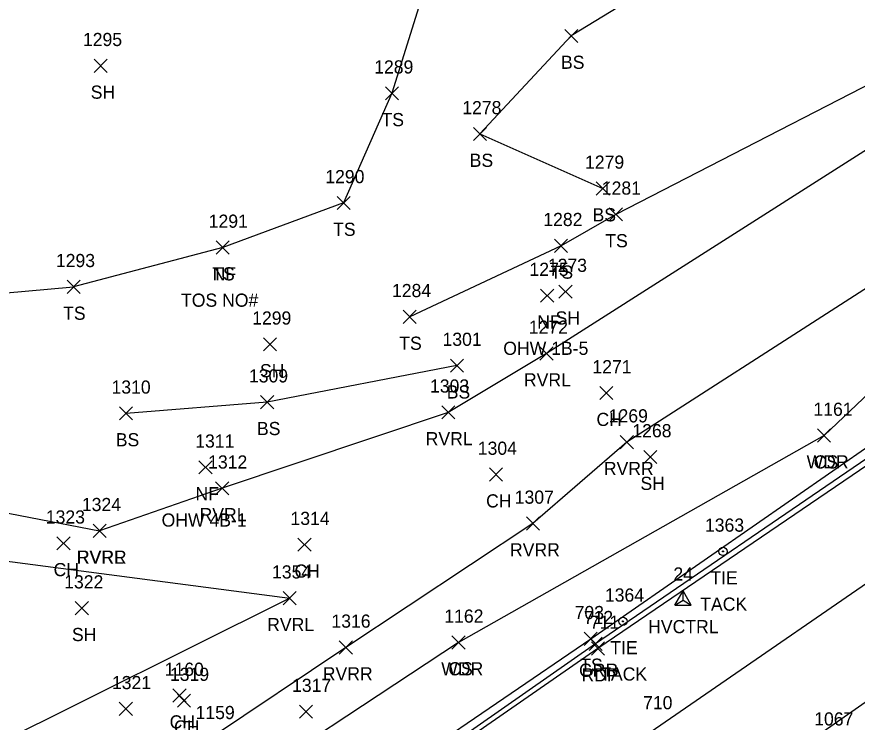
# Model space of a CAD drawing. Extents: x 1528286 to 1556263, y 492387 to 508952.
# Drawn here: x 1528810.2 to 1528937.9, y 492961.3 to 493068.5 of the extents above; entities that cross this region are included whole.
import ezdxf

# ---------------------------------------------------------------- set-up
doc = ezdxf.new("R2010")
doc.units = 0
for name, color, linetype in [('C_A', 7, 'Continuous'), ('C_C', 7, 'Continuous'), ('C_I', 7, 'Continuous'), ('CBP', 7, 'Continuous'), ('CPSM', 7, 'Continuous'), ('L_A', 7, 'Continuous'), ('L_C', 7, 'Continuous'), ('L_I', 7, 'Continuous'), ('L_TIC', 7, 'Continuous'), ('LAWA', 7, 'Continuous'), ('LAWE', 7, 'Continuous'), ('LELB', 7, 'Continuous'), ('P_A', 7, 'Continuous'), ('P_I', 7, 'Continuous'), ('P_TIC', 7, 'Continuous'), ('PET', 7, 'Continuous'), ('PRC', 7, 'Continuous'), ('R_A', 7, 'Continuous'), ('R_I', 7, 'Continuous'), ('R_TIC', 7, 'Continuous'), ('RGR', 7, 'Continuous')]:
    doc.layers.add(name, color=color, linetype=linetype)

msp = doc.modelspace()

# ---------------------------------------------------------------- linework, layer by layer
at = {"layer": 'CBP'}
for centre, radius in [((1528917.47, 492987.26), 0.625), ((1528917.47, 492987.26), 0.625), ((1528917.47, 492987.26), 0.0833), ((1528917.47, 492987.26), 0.0833), ((1528902.27, 492976.64), 0.625), ((1528902.27, 492976.64), 0.625), ((1528902.27, 492976.64), 0.0833), ((1528902.27, 492976.64), 0.0833)]:
    msp.add_circle(centre, radius, dxfattribs=at)
at = {"layer": 'CPSM'}
for p, q in [((1528910.16, 492979.12), (1528911.41, 492981.29)), ((1528910.16, 492979.12), (1528911.41, 492981.29)), ((1528912.66, 492979.12), (1528911.41, 492981.29)), ((1528911.41, 492979.84), (1528911.41, 492981.29)), ((1528912.66, 492979.12), (1528911.41, 492981.29)), ((1528911.41, 492979.84), (1528911.41, 492981.29)), ((1528910.16, 492979.12), (1528911.41, 492979.84)), ((1528910.16, 492979.12), (1528911.41, 492979.84)), ((1528910.16, 492979.12), (1528912.66, 492979.12)), ((1528910.16, 492979.12), (1528912.66, 492979.12)), ((1528911.41, 492979.84), (1528911.41, 492979.84)), ((1528911.41, 492979.84), (1528912.66, 492979.12)), ((1528911.41, 492979.84), (1528911.41, 492979.84)), ((1528911.41, 492979.84), (1528912.66, 492979.12))]:
    msp.add_line(p, q, dxfattribs=at)
at = {"layer": 'L_TIC'}
for points in [[(1528893.42, 493064.57), (1528895.42, 493066.57)], [(1528895.42, 493064.57), (1528893.42, 493066.57)], [(1528893.42, 493064.57), (1528895.42, 493066.57)], [(1528895.42, 493064.57), (1528893.42, 493066.57)], [(1528821.92, 493060.03), (1528823.92, 493062.03)], [(1528823.92, 493060.03), (1528821.92, 493062.03)], [(1528821.92, 493060.03), (1528823.92, 493062.03)], [(1528823.92, 493060.03), (1528821.92, 493062.03)], [(1528866.18, 493055.86), (1528868.18, 493057.86)], [(1528868.18, 493055.86), (1528866.18, 493057.86)], [(1528866.18, 493055.86), (1528868.18, 493057.86)], [(1528868.18, 493055.86), (1528866.18, 493057.86)], [(1528879.55, 493049.68), (1528881.55, 493051.68)], [(1528881.55, 493049.68), (1528879.55, 493051.68)], [(1528879.55, 493049.68), (1528881.55, 493051.68)], [(1528881.55, 493049.68), (1528879.55, 493051.68)], [(1528898.21, 493041.4), (1528900.21, 493043.4)], [(1528900.21, 493041.4), (1528898.21, 493043.4)], [(1528898.21, 493041.4), (1528900.21, 493043.4)], [(1528900.21, 493041.4), (1528898.21, 493043.4)], [(1528858.83, 493039.2), (1528860.83, 493041.2)], [(1528860.83, 493039.2), (1528858.83, 493041.2)], [(1528858.83, 493039.2), (1528860.83, 493041.2)], [(1528860.83, 493039.2), (1528858.83, 493041.2)], [(1528900.19, 493037.46), (1528902.19, 493039.46)], [(1528902.19, 493037.46), (1528900.19, 493039.46)], [(1528900.19, 493037.46), (1528902.19, 493039.46)], [(1528902.19, 493037.46), (1528900.19, 493039.46)], [(1528840.46, 493032.43), (1528842.46, 493034.43)], [(1528842.46, 493032.43), (1528840.46, 493034.43)], [(1528840.46, 493032.43), (1528842.46, 493034.43)], [(1528842.46, 493032.43), (1528840.46, 493034.43)], [(1528840.46, 493032.43), (1528842.46, 493034.43)], [(1528842.46, 493032.43), (1528840.46, 493034.43)], [(1528840.46, 493032.43), (1528842.46, 493034.43)], [(1528842.46, 493032.43), (1528840.46, 493034.43)], [(1528891.87, 493032.69), (1528893.87, 493034.69)], [(1528893.87, 493032.69), (1528891.87, 493034.69)], [(1528891.87, 493032.69), (1528893.87, 493034.69)], [(1528893.87, 493032.69), (1528891.87, 493034.69)], [(1528817.81, 493026.45), (1528819.81, 493028.45)], [(1528819.81, 493026.45), (1528817.81, 493028.45)], [(1528817.81, 493026.45), (1528819.81, 493028.45)], [(1528819.81, 493026.45), (1528817.81, 493028.45)], [(1528892.55, 493025.73), (1528894.55, 493027.73)], [(1528894.55, 493025.73), (1528892.55, 493027.73)], [(1528892.55, 493025.73), (1528894.55, 493027.73)], [(1528894.55, 493025.73), (1528892.55, 493027.73)], [(1528889.77, 493025.12), (1528891.77, 493027.12)], [(1528891.77, 493025.12), (1528889.77, 493027.12)], [(1528889.77, 493025.12), (1528891.77, 493027.12)], [(1528891.77, 493025.12), (1528889.77, 493027.12)], [(1528868.88, 493021.89), (1528870.88, 493023.89)], [(1528870.88, 493021.89), (1528868.88, 493023.89)], [(1528868.88, 493021.89), (1528870.88, 493023.89)], [(1528870.88, 493021.89), (1528868.88, 493023.89)], [(1528847.64, 493017.72), (1528849.64, 493019.72)], [(1528849.64, 493017.72), (1528847.64, 493019.72)], [(1528847.64, 493017.72), (1528849.64, 493019.72)], [(1528849.64, 493017.72), (1528847.64, 493019.72)], [(1528889.67, 493016.33), (1528891.67, 493018.33)], [(1528891.67, 493016.33), (1528889.67, 493018.33)], [(1528889.67, 493016.33), (1528891.67, 493018.33)], [(1528891.67, 493016.33), (1528889.67, 493018.33)], [(1528876.06, 493014.49), (1528878.06, 493016.49)], [(1528878.06, 493014.49), (1528876.06, 493016.49)], [(1528876.06, 493014.49), (1528878.06, 493016.49)], [(1528878.06, 493014.49), (1528876.06, 493016.49)], [(1528898.76, 493010.32), (1528900.76, 493012.32)], [(1528900.76, 493010.32), (1528898.76, 493012.32)], [(1528898.76, 493010.32), (1528900.76, 493012.32)], [(1528900.76, 493010.32), (1528898.76, 493012.32)], [(1528847.23, 493008.93), (1528849.23, 493010.93)], [(1528849.23, 493008.93), (1528847.23, 493010.93)], [(1528847.23, 493008.93), (1528849.23, 493010.93)], [(1528849.23, 493008.93), (1528847.23, 493010.93)], [(1528825.78, 493007.23), (1528827.78, 493009.23)], [(1528827.78, 493007.23), (1528825.78, 493009.23)], [(1528825.78, 493007.23), (1528827.78, 493009.23)], [(1528827.78, 493007.23), (1528825.78, 493009.23)], [(1528874.74, 493007.39), (1528876.74, 493009.39)], [(1528876.74, 493007.39), (1528874.74, 493009.39)], [(1528874.74, 493007.39), (1528876.74, 493009.39)], [(1528876.74, 493007.39), (1528874.74, 493009.39)], [(1528931.82, 493003.86), (1528933.82, 493005.86)], [(1528933.82, 493003.86), (1528931.82, 493005.86)], [(1528931.82, 493003.86), (1528933.82, 493005.86)], [(1528933.82, 493003.86), (1528931.82, 493005.86)], [(1528931.82, 493003.86), (1528933.82, 493005.86)], [(1528933.82, 493003.86), (1528931.82, 493005.86)], [(1528931.82, 493003.86), (1528933.82, 493005.86)], [(1528933.82, 493003.86), (1528931.82, 493005.86)], [(1528901.86, 493002.86), (1528903.86, 493004.86)], [(1528903.86, 493002.86), (1528901.86, 493004.86)], [(1528901.86, 493002.86), (1528903.86, 493004.86)], [(1528903.86, 493002.86), (1528901.86, 493004.86)], [(1528905.44, 493000.6), (1528907.44, 493002.6)], [(1528907.44, 493000.6), (1528905.44, 493002.6)], [(1528905.44, 493000.6), (1528907.44, 493002.6)], [(1528907.44, 493000.6), (1528905.44, 493002.6)], [(1528837.85, 492999.03), (1528839.85, 493001.03)], [(1528839.85, 492999.03), (1528837.85, 493001.03)], [(1528837.85, 492999.03), (1528839.85, 493001.03)], [(1528839.85, 492999.03), (1528837.85, 493001.03)], [(1528881.99, 492997.94), (1528883.99, 492999.94)], [(1528883.99, 492997.94), (1528881.99, 492999.94)], [(1528881.99, 492997.94), (1528883.99, 492999.94)], [(1528883.99, 492997.94), (1528881.99, 492999.94)], [(1528840.38, 492995.85), (1528842.38, 492997.85)], [(1528842.38, 492995.85), (1528840.38, 492997.85)], [(1528840.38, 492995.85), (1528842.38, 492997.85)], [(1528842.38, 492995.85), (1528840.38, 492997.85)], [(1528887.6, 492990.51), (1528889.6, 492992.51)], [(1528889.6, 492990.51), (1528887.6, 492992.51)], [(1528887.6, 492990.51), (1528889.6, 492992.51)], [(1528889.6, 492990.51), (1528887.6, 492992.51)], [(1528821.77, 492989.39), (1528823.77, 492991.39)], [(1528823.77, 492989.39), (1528821.77, 492991.39)], [(1528821.77, 492989.39), (1528823.77, 492991.39)], [(1528823.77, 492989.39), (1528821.77, 492991.39)], [(1528821.77, 492989.39), (1528823.77, 492991.39)], [(1528823.77, 492989.39), (1528821.77, 492991.39)], [(1528821.77, 492989.39), (1528823.77, 492991.39)], [(1528823.77, 492989.39), (1528821.77, 492991.39)], [(1528816.28, 492987.5), (1528818.28, 492989.5)], [(1528818.28, 492987.5), (1528816.28, 492989.5)], [(1528816.28, 492987.5), (1528818.28, 492989.5)], [(1528818.28, 492987.5), (1528816.28, 492989.5)], [(1528852.88, 492987.28), (1528854.88, 492989.28)], [(1528854.88, 492987.28), (1528852.88, 492989.28)], [(1528852.88, 492987.28), (1528854.88, 492989.28)], [(1528854.88, 492987.28), (1528852.88, 492989.28)], [(1528850.65, 492979.15), (1528852.65, 492981.15)], [(1528852.65, 492979.15), (1528850.65, 492981.15)], [(1528850.65, 492979.15), (1528852.65, 492981.15)], [(1528852.65, 492979.15), (1528850.65, 492981.15)], [(1528819.07, 492977.64), (1528821.07, 492979.64)], [(1528821.07, 492977.64), (1528819.07, 492979.64)], [(1528819.07, 492977.64), (1528821.07, 492979.64)], [(1528821.07, 492977.64), (1528819.07, 492979.64)], [(1528876.3, 492972.44), (1528878.3, 492974.44)], [(1528878.3, 492972.44), (1528876.3, 492974.44)], [(1528876.3, 492972.44), (1528878.3, 492974.44)], [(1528878.3, 492972.44), (1528876.3, 492974.44)], [(1528876.3, 492972.44), (1528878.3, 492974.44)], [(1528878.3, 492972.44), (1528876.3, 492974.44)], [(1528876.3, 492972.44), (1528878.3, 492974.44)], [(1528878.3, 492972.44), (1528876.3, 492974.44)], [(1528896.37, 492972.98), (1528898.37, 492974.98)], [(1528898.37, 492972.98), (1528896.37, 492974.98)], [(1528896.37, 492972.98), (1528898.37, 492974.98)], [(1528898.37, 492972.98), (1528896.37, 492974.98)], [(1528859.16, 492971.68), (1528861.16, 492973.68)], [(1528861.16, 492971.68), (1528859.16, 492973.68)], [(1528859.16, 492971.68), (1528861.16, 492973.68)], [(1528861.16, 492971.68), (1528859.16, 492973.68)], [(1528833.91, 492964.37), (1528835.91, 492966.37)], [(1528835.91, 492964.37), (1528833.91, 492966.37)], [(1528833.91, 492964.37), (1528835.91, 492966.37)], [(1528835.91, 492964.37), (1528833.91, 492966.37)], [(1528834.59, 492963.6), (1528836.59, 492965.6)], [(1528836.59, 492963.6), (1528834.59, 492965.6)], [(1528834.59, 492963.6), (1528836.59, 492965.6)], [(1528836.59, 492963.6), (1528834.59, 492965.6)], [(1528825.76, 492962.34), (1528827.76, 492964.34)], [(1528827.76, 492962.34), (1528825.76, 492964.34)], [(1528825.76, 492962.34), (1528827.76, 492964.34)], [(1528827.76, 492962.34), (1528825.76, 492964.34)], [(1528853.12, 492961.92), (1528855.12, 492963.92)], [(1528855.12, 492961.92), (1528853.12, 492963.92)], [(1528853.12, 492961.92), (1528855.12, 492963.92)], [(1528855.12, 492961.92), (1528853.12, 492963.92)]]:
    msp.add_lwpolyline(points, dxfattribs=at)
at = {"layer": 'LAWA'}
for points in [[(1528954.46, 493025.38), (1528932.82, 493004.86)], [(1528954.46, 493025.37), (1528932.82, 493004.86)], [(1528932.82, 493004.86), (1528877.3, 492973.44), (1528838.45, 492947.79), (1528805.62, 492925.4), (1528761.44, 492893.56), (1528731.58, 492876.41)], [(1528932.82, 493004.86), (1528877.3, 492973.44), (1528838.45, 492947.79), (1528805.62, 492925.4), (1528761.44, 492893.56), (1528731.58, 492876.41)]]:
    msp.add_lwpolyline(points, dxfattribs=at)
at = {"layer": 'LAWE'}
for points in [[(1528962.99, 493063.34), (1528890.67, 493017.33), (1528875.74, 493008.39), (1528841.38, 492996.85), (1528822.77, 492990.39)], [(1528962.99, 493063.34), (1528890.67, 493017.33), (1528875.74, 493008.39), (1528841.38, 492996.85), (1528822.77, 492990.39)], [(1528970.61, 493047.41), (1528902.86, 493003.86), (1528888.6, 492991.51), (1528860.16, 492972.68)], [(1528970.61, 493047.41), (1528902.86, 493003.86), (1528888.6, 492991.51), (1528860.16, 492972.68)], [(1528728.84, 493002.8), (1528789.44, 492996.84), (1528822.77, 492990.39)], [(1528728.84, 493002.8), (1528789.44, 492996.84), (1528822.77, 492990.39)], [(1528718.66, 492995.48), (1528788.19, 492988.49), (1528851.65, 492980.15), (1528805.69, 492957.26), (1528774.99, 492939.58), (1528746.81, 492927.03)], [(1528718.66, 492995.48), (1528788.19, 492988.49), (1528851.65, 492980.15), (1528805.69, 492957.26), (1528774.99, 492939.58), (1528746.81, 492927.03)], [(1528860.16, 492972.68), (1528839.47, 492958.79)], [(1528860.16, 492972.68), (1528839.47, 492958.79)]]:
    msp.add_lwpolyline(points, dxfattribs=at)
at = {"layer": 'LELB'}
for points in [[(1528924.91, 493109.51), (1528901.08, 493077.26), (1528873.56, 493077.31), (1528867.18, 493056.86), (1528859.83, 493040.2), (1528841.46, 493033.43), (1528818.81, 493027.45)], [(1528924.91, 493109.51), (1528901.08, 493077.26), (1528873.56, 493077.31), (1528867.18, 493056.86), (1528859.83, 493040.2), (1528841.46, 493033.43), (1528818.81, 493027.45)], [(1528937.74, 493092.04), (1528894.42, 493065.57), (1528880.55, 493050.68), (1528899.21, 493042.4)], [(1528937.74, 493092.04), (1528894.42, 493065.57), (1528880.55, 493050.68), (1528899.21, 493042.4)], [(1528956.32, 493066.79), (1528901.19, 493038.46), (1528892.87, 493033.69), (1528869.88, 493022.89)], [(1528956.32, 493066.79), (1528901.19, 493038.46), (1528892.87, 493033.69), (1528869.88, 493022.89)], [(1528787.67, 493024.67), (1528818.81, 493027.45)], [(1528787.67, 493024.67), (1528818.81, 493027.45)], [(1528877.06, 493015.49), (1528848.23, 493009.93), (1528826.78, 493008.23)], [(1528877.06, 493015.49), (1528848.23, 493009.93), (1528826.78, 493008.23)], [(1528932.82, 493004.86), (1528877.3, 492973.44), (1528838.45, 492947.79), (1528805.62, 492925.4)], [(1528932.82, 493004.86), (1528877.3, 492973.44), (1528838.45, 492947.79), (1528805.62, 492925.4)], [(1528511.53, 492702.85), (1528534.14, 492721.31), (1528572.64, 492751.16), (1528586.73, 492763.59), (1528600.5, 492766.35), (1528613.46, 492775.52), (1528652.2, 492802.53), (1528688.62, 492828.26), (1528710.29, 492843.12), (1528742.91, 492866.47), (1528778.71, 492891.27), (1528817.45, 492919.08), (1528857.75, 492946.94), (1528897.37, 492973.98), (1528940.29, 493003.74)], [(1528511.53, 492702.85), (1528534.14, 492721.31), (1528572.64, 492751.16), (1528586.73, 492763.59), (1528600.5, 492766.35), (1528613.46, 492775.52), (1528652.2, 492802.53), (1528688.62, 492828.26), (1528710.29, 492843.12), (1528742.91, 492866.47), (1528778.71, 492891.27), (1528817.45, 492919.08), (1528857.75, 492946.94), (1528897.37, 492973.98), (1528940.29, 493003.74)]]:
    msp.add_lwpolyline(points, dxfattribs=at)
at = {"layer": 'P_TIC'}
for points in [[(1528897.48, 492971.51), (1528899.48, 492973.51)], [(1528899.48, 492971.51), (1528897.48, 492973.51)], [(1528897.48, 492971.51), (1528899.48, 492973.51)], [(1528899.48, 492971.51), (1528897.48, 492973.51)]]:
    msp.add_lwpolyline(points, dxfattribs=at)
at = {"layer": 'PET'}
for points in [[(1528942, 493002.12), (1528898.48, 492972.51), (1528859.28, 492945.34), (1528819.08, 492917.53), (1528787.55, 492894.48), (1528780.46, 492889.94), (1528744.23, 492865.12), (1528711.17, 492841.82), (1528689.56, 492826.66), (1528653.33, 492801.52)], [(1528942, 493002.12), (1528898.48, 492972.51), (1528859.28, 492945.34), (1528819.08, 492917.53), (1528787.55, 492894.48), (1528780.46, 492889.94), (1528744.23, 492865.12), (1528711.17, 492841.82), (1528689.56, 492826.66), (1528653.33, 492801.52)], [(1528958.71, 492978.02), (1528915.24, 492947.63), (1528876.05, 492920.66), (1528835.6, 492893.02)], [(1528958.71, 492978.02), (1528915.24, 492947.63), (1528876.05, 492920.66), (1528835.6, 492893.02)]]:
    msp.add_lwpolyline(points, dxfattribs=at)
at = {"layer": 'PRC'}
msp.add_lwpolyline([(1528950.02, 492989.77), (1528907.21, 492960.29), (1528867.74, 492932.71), (1528827.79, 492905.43)], dxfattribs=at)
msp.add_lwpolyline([(1528950.02, 492989.77), (1528907.21, 492960.29), (1528867.74, 492932.71), (1528827.79, 492905.43)], dxfattribs=at)
at = {"layer": 'R_TIC'}
for points in [[(1528897.12, 492972.22), (1528899.12, 492974.22)], [(1528899.12, 492972.22), (1528897.12, 492974.22)], [(1528897.12, 492972.22), (1528899.12, 492974.22)], [(1528899.12, 492972.22), (1528897.12, 492974.22)]]:
    msp.add_lwpolyline(points, dxfattribs=at)
at = {"layer": 'RGR'}
msp.add_lwpolyline([(1528941.4, 493002.79), (1528898.12, 492973.22), (1528858.97, 492945.9), (1528818.83, 492918.12), (1528780.05, 492890.64), (1528744.15, 492865.31), (1528711.24, 492842.07), (1528689.6, 492826.87), (1528653.3, 492801.62)], dxfattribs=at)
msp.add_lwpolyline([(1528941.4, 493002.79), (1528898.12, 492973.22), (1528858.97, 492945.9), (1528818.83, 492918.12), (1528780.05, 492890.64), (1528744.15, 492865.31), (1528711.24, 492842.07), (1528689.6, 492826.87), (1528653.3, 492801.62)], dxfattribs=at)

# ---------------------------------------------------------------- texts
at = {"layer": 'C_A'}
for s, p in [('TIE', (1528915.55, 492982.26)), ('TIE', (1528915.55, 492982.26)), ('HVCTRL', (1528906.1, 492974.84)), ('HVCTRL', (1528906.1, 492974.84)), ('TIE', (1528900.35, 492971.64)), ('TIE', (1528900.35, 492971.64))]:
    msp.add_text(s, height=2, dxfattribs=at).set_placement(p)
at = {"layer": 'C_C'}
for p in [(1528914.01, 492978.26), (1528914.01, 492978.26), (1528898.81, 492967.64), (1528898.81, 492967.64)]:
    msp.add_text('TACK', height=2, dxfattribs=at).set_placement(p)
at = {"layer": 'C_I'}
for s, p in [('1363', (1528914.73, 492990.26)), ('1363', (1528914.73, 492990.26)), ('24', (1528909.94, 492982.84)), ('24', (1528909.94, 492982.84)), ('1364', (1528899.53, 492979.64)), ('1364', (1528899.53, 492979.64))]:
    msp.add_text(s, height=2, dxfattribs=at).set_placement(p)
at = {"layer": 'L_A'}
for s, p in [('BS', (1528892.86, 493060.57)), ('BS', (1528892.86, 493060.57)), ('SH', (1528821.41, 493056.03)), ('SH', (1528821.41, 493056.03)), ('TS', (1528865.59, 493051.86)), ('TS', (1528865.59, 493051.86)), ('BS', (1528878.99, 493045.68)), ('BS', (1528878.99, 493045.68)), ('BS', (1528897.65, 493037.4)), ('BS', (1528897.65, 493037.4)), ('TS', (1528858.24, 493035.2)), ('TS', (1528858.24, 493035.2)), ('TS', (1528899.59, 493033.46)), ('TS', (1528899.59, 493033.46)), ('TS', (1528839.87, 493028.43)), ('TS', (1528839.87, 493028.43)), ('NF', (1528839.94, 493028.43)), ('NF', (1528839.94, 493028.43)), ('TS', (1528891.28, 493028.69)), ('TS', (1528891.28, 493028.69)), ('TS', (1528817.22, 493022.45)), ('TS', (1528817.22, 493022.45)), ('SH', (1528892.04, 493021.73)), ('SH', (1528892.04, 493021.73)), ('NF', (1528889.25, 493021.12)), ('NF', (1528889.25, 493021.12)), ('TS', (1528868.29, 493017.89)), ('TS', (1528868.29, 493017.89)), ('SH', (1528847.13, 493013.72)), ('SH', (1528847.13, 493013.72)), ('RVRL', (1528887.23, 493012.33)), ('RVRL', (1528887.23, 493012.33)), ('BS', (1528875.5, 493010.49)), ('BS', (1528875.5, 493010.49)), ('CH', (1528898.25, 493006.32)), ('CH', (1528898.25, 493006.32)), ('BS', (1528846.67, 493004.93)), ('BS', (1528846.67, 493004.93)), ('BS', (1528825.22, 493003.23)), ('BS', (1528825.22, 493003.23)), ('RVRL', (1528872.3, 493003.39)), ('RVRL', (1528872.3, 493003.39)), ('RVRR', (1528899.37, 492998.86)), ('RVRR', (1528899.37, 492998.86)), ('WDR', (1528930.18, 492999.86)), ('WDR', (1528930.18, 492999.86)), ('CS', (1528931.26, 492999.86)), ('CS', (1528931.26, 492999.86)), ('SH', (1528904.93, 492996.6)), ('SH', (1528904.93, 492996.6)), ('NF', (1528837.33, 492995.03)), ('NF', (1528837.33, 492995.03)), ('CH', (1528881.48, 492993.94)), ('CH', (1528881.48, 492993.94)), ('RVRL', (1528837.95, 492991.85)), ('RVRL', (1528837.95, 492991.85)), ('RVRR', (1528885.11, 492986.51)), ('RVRR', (1528885.11, 492986.51)), ('RVRR', (1528819.28, 492985.39)), ('RVRR', (1528819.28, 492985.39)), ('RVRL', (1528819.33, 492985.39)), ('RVRL', (1528819.33, 492985.39)), ('CH', (1528815.77, 492983.5)), ('CH', (1528815.77, 492983.5)), ('CH', (1528852.37, 492983.28)), ('CH', (1528852.37, 492983.28)), ('RVRL', (1528848.22, 492975.15)), ('RVRL', (1528848.22, 492975.15)), ('SH', (1528818.56, 492973.64)), ('SH', (1528818.56, 492973.64)), ('WDR', (1528874.66, 492968.44)), ('WDR', (1528874.66, 492968.44)), ('CS', (1528875.74, 492968.44)), ('CS', (1528875.74, 492968.44)), ('TS', (1528895.78, 492968.98)), ('TS', (1528895.78, 492968.98)), ('RVRR', (1528856.67, 492967.68)), ('RVRR', (1528856.67, 492967.68)), ('CH', (1528833.4, 492960.37)), ('CH', (1528833.4, 492960.37)), ('CH', (1528834.08, 492959.6)), ('CH', (1528834.08, 492959.6))]:
    msp.add_text(s, height=2, dxfattribs=at).set_placement(p)
at = {"layer": 'L_C'}
for s, p in [('TOS NO#', (1528835.13, 493024.43)), ('TOS NO#', (1528835.13, 493024.43)), ('OHW 1B-5', (1528884.09, 493017.12)), ('OHW 1B-5', (1528884.09, 493017.12)), ('OHW 4B-1', (1528832.18, 492991.03)), ('OHW 4B-1', (1528832.18, 492991.03))]:
    msp.add_text(s, height=2, dxfattribs=at).set_placement(p)
at = {"layer": 'L_I'}
for s, p in [('1295', (1528820.23, 493064.03)), ('1295', (1528820.23, 493064.03)), ('1289', (1528864.48, 493059.86)), ('1289', (1528864.48, 493059.86)), ('1278', (1528877.86, 493053.68)), ('1278', (1528877.86, 493053.68)), ('1279', (1528896.51, 493045.4)), ('1279', (1528896.51, 493045.4)), ('1290', (1528857.05, 493043.2)), ('1290', (1528857.05, 493043.2)), ('1281', (1528899.06, 493041.46)), ('1281', (1528899.06, 493041.46)), ('1291', (1528839.34, 493036.43)), ('1291', (1528839.34, 493036.43)), ('1291', (1528839.34, 493036.43)), ('1291', (1528839.34, 493036.43)), ('1282', (1528890.17, 493036.69)), ('1282', (1528890.17, 493036.69)), ('1293', (1528816.12, 493030.45)), ('1293', (1528816.12, 493030.45)), ('1273', (1528890.86, 493029.73)), ('1273', (1528890.86, 493029.73)), ('1275', (1528888.07, 493029.12)), ('1275', (1528888.07, 493029.12)), ('1284', (1528867.18, 493025.89)), ('1284', (1528867.18, 493025.89)), ('1299', (1528845.94, 493021.72)), ('1299', (1528845.94, 493021.72)), ('1272', (1528887.97, 493020.33)), ('1272', (1528887.97, 493020.33)), ('1301', (1528874.86, 493018.49)), ('1301', (1528874.86, 493018.49)), ('1271', (1528897.63, 493014.32)), ('1271', (1528897.63, 493014.32)), ('1309', (1528845.45, 493012.93)), ('1309', (1528845.45, 493012.93)), ('1310', (1528824.57, 493011.23)), ('1310', (1528824.57, 493011.23)), ('1303', (1528872.96, 493011.39)), ('1303', (1528872.96, 493011.39)), ('1161', (1528931.21, 493007.86)), ('1161', (1528931.21, 493007.86)), ('1161', (1528931.21, 493007.86)), ('1161', (1528931.21, 493007.86)), ('1269', (1528900.11, 493006.86)), ('1269', (1528900.11, 493006.86)), ('1268', (1528903.7, 493004.6)), ('1268', (1528903.7, 493004.6)), ('1311', (1528837.29, 493003.03)), ('1311', (1528837.29, 493003.03)), ('1304', (1528880.22, 493001.94)), ('1304', (1528880.22, 493001.94)), ('1312', (1528839.25, 492999.85)), ('1312', (1528839.25, 492999.85)), ('1307', (1528885.83, 492994.51)), ('1307', (1528885.83, 492994.51)), ('1324', (1528820.07, 492993.39)), ('1324', (1528820.07, 492993.39)), ('1324', (1528820.07, 492993.39)), ('1324', (1528820.07, 492993.39)), ('1323', (1528814.59, 492991.5)), ('1323', (1528814.59, 492991.5)), ('1314', (1528851.76, 492991.28)), ('1314', (1528851.76, 492991.28)), ('1354', (1528848.96, 492983.15)), ('1354', (1528848.96, 492983.15)), ('1322', (1528817.38, 492981.64)), ('1322', (1528817.38, 492981.64)), ('703', (1528894.93, 492976.98)), ('703', (1528894.93, 492976.98)), ('1316', (1528857.98, 492975.68)), ('1316', (1528857.98, 492975.68)), ('1162', (1528875.13, 492976.44)), ('1162', (1528875.13, 492976.44)), ('1162', (1528875.13, 492976.44)), ('1162', (1528875.13, 492976.44)), ('1160', (1528832.65, 492968.37)), ('1160', (1528832.65, 492968.37)), ('1319', (1528833.45, 492967.6)), ('1319', (1528833.45, 492967.6)), ('1321', (1528824.64, 492966.34)), ('1321', (1528824.64, 492966.34)), ('1317', (1528852, 492965.92)), ('1317', (1528852, 492965.92)), ('1159', (1528837.34, 492961.79)), ('1159', (1528837.34, 492961.79)), ('1159', (1528837.34, 492961.79)), ('1159', (1528837.34, 492961.79)), ('1067', (1528931.33, 492960.82)), ('1067', (1528931.33, 492960.82))]:
    msp.add_text(s, height=2, dxfattribs=at).set_placement(p)
at = {"layer": 'P_A'}
msp.add_text('RDP', height=2, dxfattribs=at).set_placement((1528895.97, 492967.51))
msp.add_text('RDP', height=2, dxfattribs=at).set_placement((1528895.97, 492967.51))
at = {"layer": 'P_I'}
for s, p in [('711', (1528897.25, 492975.51)), ('711', (1528897.25, 492975.51)), ('710', (1528905.33, 492963.29)), ('710', (1528905.33, 492963.29))]:
    msp.add_text(s, height=2, dxfattribs=at).set_placement(p)
at = {"layer": 'R_A'}
msp.add_text('GRR', height=2, dxfattribs=at).set_placement((1528895.6, 492968.22))
msp.add_text('GRR', height=2, dxfattribs=at).set_placement((1528895.6, 492968.22))
at = {"layer": 'R_I'}
msp.add_text('712', height=2, dxfattribs=at).set_placement((1528896.32, 492976.22))
msp.add_text('712', height=2, dxfattribs=at).set_placement((1528896.32, 492976.22))

doc.saveas('drawing.dxf')
